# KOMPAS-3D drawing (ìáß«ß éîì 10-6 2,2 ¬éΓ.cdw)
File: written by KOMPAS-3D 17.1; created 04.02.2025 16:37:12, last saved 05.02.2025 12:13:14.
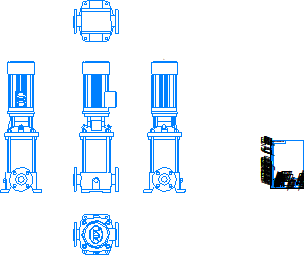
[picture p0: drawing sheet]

Sheet 1: A4, portrait

Title block, sheet 1: name: Насос ВМН 10-6 2,2 / кВт; designation: Насос ВМН 10-6 2,2 кВт; material: Сталь 10  ГОСТ 1050-2013; mass: 140,36; sheets: 1; sheet format: A4; stored path: \\adlc.lan\data\АДЛ_ПКД\3D-модели\ADL production\Насосы ГРАНПАМП\Насосы ВМН\ВМН10\KOMPAS 3D\Насос ВМН 10-6 2,2 кВт.cdw

Views: Вид 1, Спереди, Проекционный вид 2, Проекционный вид 3, Проекционный вид 4, Проекционный вид 5
Referenced files in \\adlc.lan\data\АДЛ_ПКД\3D-модели\ADL production\Насосы ГРАНПАМП\Насосы ВМН\ВМН10\KOMPAS 3D\: ВМН 10-6 2,2 кВт.m3d, Насос ВМН 10-6 2,2 кВт.m3d
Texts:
  Andrey
  АДЛ
Dimensions and other numbers on the sheet: 1:1; 1; 140,36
